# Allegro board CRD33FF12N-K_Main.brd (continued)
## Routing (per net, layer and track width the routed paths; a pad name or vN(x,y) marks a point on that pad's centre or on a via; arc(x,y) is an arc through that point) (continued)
DC_L_+: length 139.9
  TOP w0.254: v1(149.78,3.36) 149.78,2.94 150.96,1.76 262.25,1.76 263.01,2.52 J6.3
  BOTTOM w0.254: v1(149.78,3.36) 149.15,3.99 147.34,3.99 136.79,14.53 136.79,19.68 R161.2
DC_L_-: length 142.4
  TOP w0.254: J6.5 265.21,3.99 262.47,1.25 150.75,1.25 148.75,3.25 v1(148.62,3.25)
  BOTTOM w0.254: v1(148.62,3.25) 147.36,3.25 136.28,14.32 136.28,19.79 R117.2
DC_N: length 99
  ART04 w0.508: 407.04,36.45 407.04,34.42 402.47,29.84 402.47,18.03 397.19,12.75 378.65,12.75 v1(378.59,12.7)
  BOTTOM w0.254: 156.74,178.45 157.23,177.96 v1(157.78,177.96)
  BOTTOM w0.508: R130.2 218.79,193.37 C45.2 ; R99.1 v1(240.93,25.03) ; C50.1 207.21,43.78 206.35,42.93 R131.1 ; R87.1 171.44,40.55 174.26,43.37 174.26,43.49 174.66,43.9 174.78,43.9 C49.1 ; C46.2 178.61,198.9 178.61,209.97 R100.1 ; v1(378.59,12.7) 377.18,11.29 R139.1
  vias: v1(144.9,84.97) v1(144.9,83.27) v1(145.72,85.88) v1(147.42,85.88) v1(147.84,65.86) v1(147.9,64.64) v1(148.79,63.88) v1(149.05,67.06) v1(149.13,166.12) v1(149.19,164.9) v1(150.08,164.13) v1(150.19,63.75) v1(150.34,167.31) v1(150.57,66.8) v1(150.75,145.76) v1(151.08,64.39) v1(151.21,65.79) v1(151.48,164.01) v1(151.86,167.06) v1(152.12,145.76) v1(152.37,164.64) v1(152.5,166.04) v1(155.08,53.28) v1(155.08,43.08) v1(155.21,52.26) v1(155.21,42.06) v1(155.66,189.11) v1(155.66,178.91) v1(155.74,188.02) v1(155.74,177.82) v1(156.1,53.91) v1(156.1,51.75) v1(156.1,43.71) v1(156.1,41.55) v1(156.39,189.75) v1(156.39,179.55) v1(156.73,187.47) v1(156.73,177.27) v1(157.11,53.41) v1(157.11,52.26) v1(157.11,43.21) v1(157.11,42.06) v1(157.44,189.51) v1(157.44,179.31) v1(157.78,188.16) v1(166.22,84.97) v1(166.22,83.27) v1(167.04,85.88) v1(168.74,85.88) v1(171.96,145.76) v1(173.33,145.76) v1(174.05,43.97) v1(174.09,45.44) v1(174.94,43.21) v1(175.2,46.38) v1(176.34,43.08) v1(176.72,46.13) v1(177.23,43.72) v1(177.36,45.11) v1(183.9,192.69) v1(183.86,191.22) v1(184.75,190.46) v1(185.01,193.63) v1(186.15,190.33) v1(186.53,193.38) v1(187.04,190.96) v1(187.17,192.36) v1(187.54,84.97) v1(187.54,83.27) v1(188.36,85.88) v1(190.06,85.88) v1(193.17,145.76) v1(194.54,145.76) v1(205.63,45.44) v1(205.59,43.97) v1(206.48,43.21) v1(206.74,46.38) v1(207.88,43.08) v1(208.26,46.13) v1(208.77,43.72) v1(208.89,45.11) v1(215.84,191.22) v1(215.88,192.69) v1(216.73,190.46) v1(216.98,193.63) v1(218.13,190.33) v1(218.51,193.38) v1(219.02,190.96) v1(219.14,192.36) v1(243.05,198.23) v1(243.05,188.33) v1(243.09,199.7) v1(243.09,189.8) v1(243.94,197.47) v1(243.94,187.57) v1(244.19,200.64) v1(244.19,190.74) v1(245.33,197.34) v1(245.33,187.44) v1(245.71,200.39) v1(245.71,190.49) v1(246.22,197.97) v1(246.22,188.07) v1(246.35,199.37) v1(246.35,189.47) v1(248.05,198.23) v1(248.05,188.33) v1(248.09,199.7) v1(248.09,189.8) v1(248.94,197.47) v1(248.94,187.57) v1(249.19,200.64) v1(249.19,190.74) v1(250.33,197.34) v1(250.33,187.44) v1(250.55,21.53) v1(250.55,16.53) v1(250.59,23) v1(250.59,18) v1(250.71,200.39) v1(250.71,190.49) v1(251.22,197.97) v1(251.22,188.07) v1(251.35,199.37) v1(251.35,189.47) v1(251.44,20.77) v1(251.44,15.77) v1(251.69,23.94) v1(251.69,18.94) v1(252.83,20.64) v1(252.83,15.64) v1(253.22,23.69) v1(253.22,18.69) v1(253.72,21.28) v1(253.72,16.28) v1(253.85,22.67) v1(253.85,17.67) v1(260.45,21.53) v1(260.45,16.53) v1(260.49,23) v1(260.49,18) v1(261.34,20.77) v1(261.34,15.77) v1(261.59,23.94) v1(261.59,18.94) v1(262.73,20.64) v1(262.73,15.64) v1(263.12,23.69) v1(263.12,18.69) v1(263.62,21.28) v1(263.62,16.28) v1(263.75,22.67) v1(263.75,17.67) v1(412.42,188.26) v1(412.42,183.26) v1(412.67,189.78) v1(412.67,184.78) v1(413.36,187.16) v1(413.36,182.16) v1(413.69,190.42) v1(413.69,185.42) v1(414.83,187.12) v1(414.83,182.12) v1(415.08,190.29) v1(415.08,185.29) v1(415.59,188.01) v1(415.59,183.01) v1(415.72,189.4) v1(415.72,184.4) v1(418.98,164.59) v1(418.98,133.48) v1(418.98,101.73) v1(418.98,69.98) v1(418.98,38.86) v1(419.11,163.58) v1(419.11,132.46) v1(419.11,100.71) v1(419.11,68.96) v1(419.11,37.85) v1(420,165.23) v1(420,163.07) v1(420,134.11) v1(420,131.95) v1(420,102.36) v1(420,100.2) v1(420,70.61) v1(420,68.45) v1(420,39.5) v1(420,37.34) v1(421.01,164.72) v1(421.01,163.58) v1(421.01,133.6) v1(421.01,132.46) v1(421.01,101.85) v1(421.01,100.71) v1(421.01,70.1) v1(421.01,68.96) v1(421.01,38.99) v1(421.01,37.85) v1(422.32,188.26) v1(422.32,183.26) v1(422.57,189.78) v1(422.57,184.78) v1(423.26,187.16) v1(423.26,182.16) v1(423.59,190.42) v1(423.59,185.42) v1(424.73,187.12) v1(424.73,182.12) v1(424.98,190.29) v1(424.98,185.29) v1(425.49,188.01) v1(425.49,183.01) v1(425.62,189.4) v1(425.62,184.4) v1(427.91,188.39) v1(427.91,183.39) v1(428.16,189.91) v1(428.16,184.91) v1(428.85,187.28) v1(428.85,182.28) v1(429.18,190.55) v1(429.18,185.55) v1(430.32,187.24) v1(430.32,182.24) v1(430.58,190.42) v1(430.58,185.42) v1(431.09,188.13) v1(431.09,183.13) v1(431.21,189.53) v1(431.21,184.53) v1(437.81,188.39) v1(437.81,183.39) v1(438.06,189.91) v1(438.06,184.91) v1(438.75,187.28) v1(438.75,182.28) v1(439.08,190.55) v1(439.08,185.55) v1(440.22,187.24) v1(440.22,182.24) v1(440.48,190.42) v1(440.48,185.42) v1(440.99,188.13) v1(440.99,183.13) v1(441.11,189.53) v1(441.11,184.53) v1(443.28,188.26) v1(443.28,183.26) v1(443.53,189.78) v1(443.53,184.78) v1(444.22,187.16) v1(444.22,182.16) v1(444.55,190.42) v1(444.55,185.42) v1(445.69,187.12) v1(445.69,182.12) v1(445.94,190.29) v1(445.94,185.29) v1(446.45,188.01) v1(446.45,183.01) v1(446.58,189.4) v1(446.58,184.4) v1(453.18,188.26) v1(453.18,183.26) v1(453.43,189.78) v1(453.43,184.78) v1(454.12,187.16) v1(454.12,182.16) v1(454.45,190.42) v1(454.45,185.42) v1(455.59,187.12) v1(455.59,182.12) v1(455.84,190.29) v1(455.84,185.29) v1(456.35,188.01) v1(456.35,183.01) v1(456.48,189.4) v1(456.48,184.4)
DRV_COM1: length 13.9
  ART04 w0.508: v1(82.99,160.32) 76.11,160.32 74.03,162.4 v1(74.03,162.41)
  BOTTOM w0.381: R12.2 v1(81.89,156.44)
  BOTTOM w0.508: R14.2 101.89,155.83 v1(101.89,156.62) ; R24.2 v1(122.45,156.46)
  vias: v1(82.13,159.31) v1(83.57,159.31)
DRV_COM2: length 16.3
  BOTTOM w0.508: v1(147.89,156.16) 148.77,155.28 R42.2 ; R44.2 191.45,155.97 v1(191.45,156.08) ; 168.46,160.27 168.74,160.27 169.23,159.78 174.33,159.78 174.62,159.5 177.52,159.5 178.71,160.69 C108.1 ; R43.2 170.94,155.1 169.65,156.39 v1(169.27,156.39)
  vias: v1(167.32,159.33) v1(168.03,159.33)
DRV_COM3: length 22.4
  BOTTOM w0.508: C120.1 190.71,66.53 187.23,70 183.42,70 182.79,70.63 182.79,72.36 182.26,72.89 180.62,72.89 180.29,72.56 ; R73.2 v1(194.79,75.8) ; R69.2 153.2,78.21 v1(152,78.21) ; v1(174.53,77.62) 175.31,77.62 R71.2
  vias: v1(178.42,73.13) v1(179.05,73.13)
DRV_COM4: length 37.8
  BOTTOM w0.508: R124.2 125.57,76.71 v1(119.51,76.71) ; v1(107.17,75.9) 105.94,77.12 R123.2 ; v1(108.31,73.25) 108.36,73.25 ; 108.36,73.25 v1(108.95,73.25) 108.9,73.2 108.9,73.07 108.67,72.85 ; 108.36,73.25 108.67,72.95 108.67,72.85 ; 108.67,72.85 C40.2 106.97,72.58 C30.1 106.94,72.6 106.94,72.9 106.07,73.77 101.78,73.77 99.69,71.68 99.69,68.84 99.16,68.31 88.37,68.31 C128.1 ; v1(85.2,78.38) 84.25,77.44 R122.2
DRV_COM5: length 41.9
  BOTTOM w0.254: 251.85,158.88 251.85,158.89 ; 236.1,159 236.23,159.13
  BOTTOM w0.508: C18.1 C12.2 ; R34.2 244.5,157.79 243.92,158.37 236.74,158.37 236.56,158.54 ; R32.2 224.86,157.54 226.07,158.75 234.7,158.75 ; 236.23,159.13 236.25,159.13 236.28,159.16 236.84,159.16 236.87,159.13 236.97,159.03 247.38,159.03 248.55,157.86 250.83,157.86 251.85,158.88
DRV_COM6: length 49.3
  BOTTOM w0.508: C135.1 247.22,68.24 245.36,70.09 240.78,70.09 239.1,71.77 239.09,71.77 237.59,73.26 235.89,73.26 235.26,72.63 235.26,72.39 ; 234.13,72.51 234.13,73.04 235.68,74.59 246.47,74.59 R63.2 ; R61.2 227.05,78.49 232.18,78.49 234.78,75.9 234.78,74.91 233.21,73.34 233.21,72.26
DRV_G11: length 16.4
  BOTTOM w0.508: R9.1 77.28,152.47 R11.2 ; R11.2 74.82,152.44 R17.1 ; R11.2 77.73,151.95 Q11.4 77.73,146.6 75.79,144.65 R91.2 75.79,143.62 76.63,142.77 R94.2
DRV_G12: length 15.7
  BOTTOM w0.508: R5.1 R1.1 R2.2 98.94,152.37 Q12.4 98.94,146.1 97.6,144.76 R93.2 97.6,143.64 98.52,142.72 R173.2
DRV_G13: length 15.9
  BOTTOM w0.508: R169.2 119.47,142.78 118.66,143.59 R92.2 118.66,144.68 120.15,146.18 Q13.4 120.15,152.24 R8.2 R6.1 R4.1
DRV_G21: length 15.7
  BOTTOM w0.508: R37.1 R28.2 R27.1 146.48,148.21 Q21.4 146.28,145.81 145.41,144.93 R174.2 145.41,143.39 145.97,142.82 R177.2
DRV_G22: length 15.7
  BOTTOM w0.508: R31.2 168,152.14 ; 168,152.14 168,151.59 167.49,151.08 Q22.4 167.49,145.7 166.59,144.79 R176.2 166.59,143.33 167.07,142.85 R178.2 ; 168,152.14 R29.1 R36.1
DRV_G23: length 15.3
  BOTTOM w0.508: 189.21,152.26 R35.1 R40.2 ; 189.21,152.26 188.7,151.76 Q23.4 188.7,146.04 187.77,145.11 R175.2 187.77,143.87 188.7,142.95 R170.2 ; 189.21,152.26 R38.1
DRV_G31: length 16.4
  BOTTOM w0.508: R182.2 157.9,89.38 159.12,88.17 R179.2 159.12,87.5 158.26,86.64 157.32,86.64 156.78,86.1 Q31.4 156.42,83.8 156.42,80.19 R45.1 158.65,80.14 158.71,80.19 R48.2 R64.1
DRV_G32: length 15.5
  BOTTOM w0.508: Q32.4 178.09,85.83 179.68,87.42 R118.2 179.68,88.34 178.73,89.29 R183.2 ; Q32.4 178.09,80.15 R51.1 R55.2 R62.1 ; Q32.4 178.03,84.1
DRV_G33: length 15.3
  BOTTOM w0.508: R66.1 199.41,80.09 Q33.4 199.41,85.99 200.95,87.53 R180.2 200.95,88.24 199.88,89.31 R171.2 ; R66.1 R68.2 ; R66.1 R58.1
DRV_G41: length 15.9
  BOTTOM w0.508: R187.2 88.1,89.4 88.86,88.64 R184.2 88.86,87.51 87.89,86.55 Q41.4 87.89,81.72 86.54,80.36 R77.2 R74.1 R90.1
DRV_G42: length 16.6
  BOTTOM w0.508: R78.1 109.21,81.13 Q42.4 109.21,85.43 110.17,86.39 110.17,87.76 R186.2 110.15,88.64 109.58,89.2 R188.2 ; R78.1 R79.2 112.78,80.14 R84.1 ; R78.1 108.26,80.11 109.28,80.11
DRV_G43: length 15.1
  BOTTOM w0.508: R95.1 130.53,80.25 Q43.4 130.53,86.12 131.51,87.09 R185.2 131.51,88.58 130.78,89.31 R172.2 ; R95.1 130.35,80.1 R121.2 ; R95.1 132.63,80.09 R80.1
DRV_G51: length 11
  BOTTOM w0.508: 220.16,152.49 R16.1 ; 220.16,152.49 220.04,152.49 219.83,152.29 Q51.4 219.83,145.53 220.38,144.99 R83.2 ; 220.16,152.49 R18.2
DRV_G52: length 10.8
  BOTTOM w0.508: 241.55,152.24 241.09,152.24 241.09,152.24 R15.1 ; 241.55,152.24 241.55,151.27 241.04,150.77 Q52.4 241.6,147.45 R85.2 ; 241.55,152.24 R23.2
DRV_G61: length 10.5
  BOTTOM w0.508: R53.2 230.4,79.96 R50.1 230.39,80.87 229.89,81.37 Q61.4 229.89,87.65 R88.2
DRV_G62: length 10.4
  BOTTOM w0.508: R49.1 R59.2 251.2,80.28 Q62.4 251.2,87.5 R89.2
DRV_GATE1: length 7.1
  ART04 w0.508: v1(85.6,163.75) v1(83.52,163.75)
  BOTTOM w0.508: R22.1 85.98,162.63 85.98,163.38 v1(85.6,163.75) ; U1.6 v1(83.52,163.75)
DRV_GATE2: length 10.3
  BOTTOM w0.508: U3.6 168.38,163.9 167.56,164.72 164.93,164.72 162.71,162.5 R39.1
DRV_GATE3: length 20.1
  ART05 w0.508: v1(188.86,69.65) 185.34,66.13 v1(182.12,66.13)
  BOTTOM w0.508: R67.1 186.91,71.59 v1(188.86,69.65) ; v1(182.12,66.13) 179.8,66.13 178.04,67.9 U4.6
DRV_GATE4: length 11.2
  ART05 w0.508: v1(107.34,69.24) 107.34,68.99 107.84,68.48 109.02,68.48 109.53,68.99 109.53,71.14 v1(112.03,73.63)
  BOTTOM w0.508: U6.6 v1(107.34,69.24) ; v1(112.03,73.63) R96.1
DRV_Q1_-3V: length 26
  BOTTOM w0.508: C7.1 80.54,160.84 80.98,161.29 U1.8 80.98,163.07 80.43,163.62 C5.1 75.88,161.38 68.01,161.38 66.2,163.18 C91.2
DRV_Q2_+15V: length 4
  BOTTOM w0.254: 178.85,166.09 C101.2
  BOTTOM w0.508: 178.85,166.09 178.34,165.58 R191.1
DRV_Q2_-3V: length 28.4
  ART05 w0.508: v1(177.16,158.69) 176.89,158.97 v1(176.89,160.32) 175.37,161.83 167.87,161.83 v1(165.56,159.53)
  BOTTOM w0.508: v1(177.16,158.69) 180,158.69 181.51,160.21 C108.2 ; v1(165.56,159.53) C20.1 165.56,160.91 165.84,161.18 U3.8 ; C17.1 175.37,161.83 v1(176.89,160.32)
DRV_Q3_+15V: length 9.3
  BOTTOM w0.508: C110.2 188.85,58.25 188.34,58.76 188.34,61.43 R193.1
DRV_Q3_-3V: length 17
  ART05 w0.508: v1(193.13,66.84) 189.18,66.84 v1(188.95,67.07)
  BOTTOM w0.508: C29.1 181.6,71.38 180.58,70.35 U4.8 180.58,69.09 180.83,68.83 C25.1 183.73,69.07 186.95,69.07 v1(188.95,67.07)
DRV_Q4_+15V: length 11.1
  BOTTOM w0.508: C128.2 88.77,70.71 89.29,70.71 90.38,69.62 R194.1
DRV_Q4_-3V: length 30.8
  BOTTOM w0.254: C40.1 110.19,72.57 110.23,72.53
  BOTTOM w0.508: C138.2 86.8,64.98 89.87,64.98 91.71,66.82 99.88,66.82 100.94,67.87 C34.1 109.14,67.87 109.88,68.61 U6.8 109.88,72.05 110.23,72.41 110.23,72.59
DRV_Q5_+15V: length 2.9
  BOTTOM w0.508: R190.1 248.34,159.95 C118.1
DRV_Q5_-3V: length 39.8
  BOTTOM w0.508: C18.2 233.37,160.83 233.62,161.09 U2.8 233.62,163.65 234.66,164.69 239.02,164.69 C16.2 241.24,163.53 247.76,170.05 256.24,170.05 257.02,169.28 257.02,163.1 256.54,162.62 C126.2
DRV_Q6_-3V: length 28.2
  ART05 w0.508: v1(240.67,71.36) 239.16,71.36 v1(238.76,70.95)
  BOTTOM w0.508: U5.8 235.7,70.52 236.47,71.29 236.47,72.11 236.47,72.12 C35.2 237.3,72.16 237.34,72.12 237.6,72.12 v1(238.76,70.95) 239.34,70.38 C33.2 ; C144.2 251.14,62.96 251.9,63.72 251.9,67.22 247.77,71.36 v1(240.67,71.36)
DRV_S11: length 11.2
  BOTTOM w0.508: R94.1 78.98,142.77 80.15,143.94 C19.1 80.15,147.89 Q11.3 80.27,150.65 81.89,152.27 R12.1
DRV_S12: length 10.8
  BOTTOM w0.508: R173.1 100.79,142.72 101.99,143.92 C54.1 101.99,144.91 101.48,145.42 Q12.3 101.48,152.26 R14.1
DRV_S13: length 10.9
  BOTTOM w0.508: R169.1 122.31,142.78 123.03,143.49 C39.1 123.03,145.03 122.69,145.36 Q13.3 122.69,152.12 R24.1
DRV_S21: length 11
  BOTTOM w0.508: R42.1 148.82,152.31 Q21.3 148.82,145.56 149.8,144.59 C64.1 149.8,143.53 149.09,142.82 R177.1
DRV_S22: length 11.3
  BOTTOM w0.508: R43.1 170.03,151.23 Q22.3 170.03,145.66 170.98,144.71 C66.1 170.98,143.18 170.65,142.85 R178.1
DRV_S23: length 11.1
  BOTTOM w0.508: R170.1 191.27,142.95 192.14,143.82 C65.1 192.14,144.9 191.24,145.79 Q23.3 191.24,150.93 192.35,152.03 R44.1
DRV_S31: length 10.2
  BOTTOM w0.508: R69.1 154.24,80.31 Q31.3 154.24,87.34 C70.1 154.75,88.1 156.04,89.38 R182.1
DRV_S32: length 10
  BOTTOM w0.508: R71.1 175.64,84.07 Q32.3 175.55,87.66 C146.1 175.37,88.08 176.58,89.29 R183.1
DRV_S33: length 11.3
  BOTTOM w0.508: R73.1 196.87,82.13 Q33.3 196.87,87.57 C145.1 196.59,88.55 197.34,89.31 198.03,89.31
DRV_S41: length 11.2
  BOTTOM w0.508: R187.1 85.11,89.4 84.32,88.61 C162.1 84.32,87.16 85.35,86.13 Q41.3 85.35,81.25 R122.1
DRV_S42: length 10.9
  BOTTOM w0.508: 105.71,87.78 105.71,87.13 106.67,86.17 Q42.3 107.03,83.8 107.03,81.23 R123.1 ; 105.71,87.78 C164.1 105.71,87.78 ; 105.71,87.78 105.71,88.05 106.86,89.2 R188.1
DRV_S43: length 11.3
  BOTTOM w0.508: R172.1 127.89,89.31 127.11,88.52 C163.2 127.11,86.98 127.99,86.09 127.99,82.13 126.16,80.3 R124.1
DRV_S51: length 9.5
  BOTTOM w0.508: R83.1 221.89,144.9 222.37,145.38 Q51.3 222.37,150.1 224.76,152.49 R32.1
DRV_S52: length 8.7
  BOTTOM w0.508: R34.1 244.5,152.14 243.48,151.12 243.48,148.11 Q52.3 243.12,147.55 R85.1
DRV_S61: length 8.9
  BOTTOM w0.508: R88.1 227.35,87.1 Q61.3 227.29,84.11 227.29,81.54 R61.1
DRV_S62: length 8.3
  BOTTOM w0.508: R89.1 248.66,87.27 Q62.3 248.66,80.54 R63.1
FAN_GND: length 0
  vias: v1(4.78,175.69) v1(6.23,174.65) v1(7.81,173.56)
GATE5: length 31.2
  ART04 w0.508: v1(243.57,157.2) 240,157.2 v1(236.16,161.04) 235.27,161.93 233.56,161.93 v1(232.54,160.91)
  BOTTOM w0.508: R23.1 242.21,156.56 242.72,157.07 243.44,157.07 v1(243.57,157.2) ; R18.1 222.45,156.81 225.65,160.02 231.66,160.02 v1(232.54,160.91) ; U2.6 v1(236.16,161.04)
GATE6: length 32.4
  ART05 w0.508: v1(230.53,71.18) 230.54,71.17 v1(233.16,71.17) 233.22,71.17 234.09,70.3 236.52,70.3 238.54,72.32 v1(239.82,72.32)
  BOTTOM w0.508: v1(230.53,71.18) 230.53,73.72 228.13,76.12 R53.1 ; v1(239.82,72.32) 246.48,72.32 251.42,77.27 R59.1 ; U5.6 v1(233.16,71.17)
GGND: length 745.5
  TOP w0.762: v1(220.89,23.72) 219.39,23.72 218.2,22.53 v1(216.16,22.53) ; v1(197.3,179.86) 199.72,179.86 201.14,181.28 257.12,181.28 260.88,177.53 v1(260.88,176.46)
  GND02 w0.762: v1(197.3,179.86) 177.63,179.86 175.37,182.13 175.37,202.61 166.61,211.37 37.64,211.37 32.95,206.68 32.95,182.36 v1(36,179.31)
  ART03 w0.508: J5.6 162.36,7.46 162.36,10.03
  ART03 w0.762: v1(216.16,22.53) 200.05,22.53 191.57,14.05 166.38,14.05 162.36,10.03 ; J5.6 161.08,6 159.51,4.44 153.15,4.44 145.5,12.09 113.74,12.09 112.24,10.59 107.56,10.59 106.97,11.19 106.97,11.2 106.71,11.46 v1(106.71,12.78) ; v1(57.63,59.52) 57.63,59.55 56.53,60.65 56.53,96.8 69.26,109.53 69.26,123.02 54.21,138.07 54.21,158.75 59.52,164.05 v1(59.77,164.05)
  BOTTOM w0.762: v1(106.71,12.78) 106.71,17.42 103.16,20.97 69.54,20.97 55.54,34.97 55.54,57.43 v1(57.63,59.52) ; C139.2 239.53,31.41 237.49,31.41 229.79,23.72 v1(220.89,23.72) ; v1(197.3,179.86) 197.34,179.83 197.34,177.56 198.39,176.51 C103.2 ; v1(36,179.31) 36.12,179.2 36.12,176.61 36.92,175.81 58.84,175.81 60.45,174.2 60.45,164.73 v1(59.77,164.05) 59.36,164.05 58.58,164.83 57.75,164.83 ; v1(260.88,176.46) C121.2
  BOTTOM w0.78: C112.2 217.22,48.45 217.22,25.81 216.16,24.75 v1(216.16,22.53)
IGND: length 99
  TOP w0.762: J2.1 81.31,6.99 86.15,6.99 86.69,6.45 96.32,6.45 98.04,4.74 C157.2 117.53,4.74 123.28,10.49 149.93,10.49 152.04,12.6 164.9,12.6 167.87,9.63 167.87,7.89 J5.2
IL+: length 132.9
  TOP w0.254: R75.1 380.14,6.59 379.83,6.59 379.82,6.59 376.02,6.59 369.25,13.35 362.22,13.35 359.36,16.21 272.29,16.21 265.82,9.74 262.94,9.74 260.98,7.78 260.1,7.78 259.23,6.9 259.23,5.23 J6.1
IL-: length 128.2
  TOP w0.254: J6.2 263.04,9.09 266.04,9.09 272.64,15.7 359.15,15.7 362.01,12.84 369.04,12.84 375.81,6.08 380.14,6.08 R76.1
MID_N:
  vias: v1(76.02,84.97) v1(76.02,83.27) v1(76.93,82.45) v1(78.63,82.45) v1(97.34,84.97) v1(97.34,83.27) v1(98.25,82.45) v1(99.95,82.45) v1(118.65,84.97) v1(118.65,83.27) v1(119.56,82.45) v1(121.27,82.45) v1(151.08,81.91) v1(152.45,81.91) v1(172.4,81.91) v1(173.77,81.91) v1(193.71,81.91) v1(195.08,81.91) v1(224.19,81.91) v1(225.56,81.91) v1(245.51,81.91) v1(246.88,81.91)
MID_P:
  vias: v1(82.06,150.27) v1(83.43,150.27) v1(103.27,150.27) v1(104.64,150.27) v1(124.48,150.27) v1(125.85,150.27) v1(155.55,149.73) v1(157.25,149.73) v1(158.16,148.91) v1(158.16,147.2) v1(176.76,149.73) v1(178.46,149.73) v1(179.37,148.91) v1(179.37,147.2) v1(197.97,149.73) v1(199.67,149.73) v1(200.58,148.91) v1(200.58,147.2) v1(229.1,149.73) v1(230.8,149.73) v1(231.71,148.91) v1(231.71,147.2) v1(250.31,149.73) v1(252.01,149.73) v1(252.92,148.91) v1(252.92,147.2)
NETC1_2: length 5.6
  BOTTOM w0.508: R3.2 77.6,173.66 C2.1 C1.2 80.68,173.58 80.98,173.28 U1.1
NETC3_2: length 8.8
  BOTTOM w0.254: R10.2 86.14,173.96 R7.2 86.14,175.55 85.28,176.4 83.55,176.4 83.15,176.01 C3.2 83.1,175.31 82.25,174.46 U1.2
NETC4_2: length 14.5
  BOTTOM w0.508: R189.2 76.2,163.79 77.82,165.4 C5.2 83.84,165.4 84.79,164.44 U1.5 84.79,161.28 85.1,160.97 85.38,160.69 C4.2
NETC8_2: length 5.5
  BOTTOM w0.508: U2.1 233.62,173.19 233.37,173.44 C8.2 C9.1 229.94,174.84 R19.2
NETC10_2: length 8.2
  BOTTOM w0.254: U2.2 234.89,174.12 C10.2 236.04,175.31 236.84,176.11 238.79,176.11 239.04,175.86 R21.2 239.05,175.28 R25.2
NETC11_2: length 5.4
  BOTTOM w0.508: R26.2 162.35,175.3 C13.1 C11.2 165.33,173.78 165.84,173.28 U3.1
NETC12_1: length 10.9
  BOTTOM w0.508: R190.2 243.27,161.14 242.66,161.75 C16.1 239.76,161.75 238.37,163.14 237.86,163.14 237.43,162.72 U2.5 237.43,160.85 237.94,160.34 C12.1
NETC14_2: length 8.8
  BOTTOM w0.254: U3.2 167.11,174.19 168.31,175.4 C14.2 168.31,175.96 168.82,176.46 170.92,176.46 171.36,176.03 R30.2 171.36,174.05 R33.2
NETC15_2: length 9.1
  BOTTOM w0.508: C15.2 169.95,160.82 169.95,161.36 169.65,161.67 U3.5 169.65,164.54 170.69,165.58 R191.2 172.46,165.57 C17.2
NETC19_2: length 1.3
  BOTTOM w0.508: R91.1 C19.2
NETC21_2: length 15.8
  BOTTOM w0.508: R193.2 183.61,66.94 C25.2 183.12,66.68 183.12,65.75 182.61,65.25 178.94,65.25 176.77,67.42 U4.5 176.77,71.72 C21.2
NETC22_2: length 5.3
  BOTTOM w0.508: U4.1 181.07,58.7 C22.2 C23.1 184.09,58.66 R41.2
NETC24_2: length 8.6
  BOTTOM w0.254: U4.2 179.31,58.09 C24.2 178.13,56.31 177.87,56.05 175.36,56.05 175.1,56.31 R46.2 175.1,58.32 R52.2
NETC26_2: length 5.5
  BOTTOM w0.508: R54.2 238.72,58.03 C27.1 C26.2 236.2,58.08 235.7,58.58 U5.1
NETC30_2: length 7.6
  BOTTOM w0.508: R194.2 102.13,69.62 102.16,69.65 C34.2 103.5,69.65 104.48,70.63 U6.5 106.07,71.81 105.67,72.2 105.67,72.36 C30.2
NETC31_2: length 8.7
  BOTTOM w0.254: R60.2 230.29,57.71 230.28,57.7 230.28,57.54 230.26,57.53 R57.2 230.26,56.55 230.87,55.94 232.36,55.94 233.24,56.82 C31.2 233.94,56.92 234.43,57.41 U5.2
NETC32_1: length 14
  BOTTOM w0.508: C32.1 231.91,71.34 231.9,71.34 231.9,71.13 231.89,71.12 U5.5 231.89,68.48 232.98,67.38 C33.1 240.67,67.38 R192.2
NETC36_2: length 5.4
  BOTTOM w0.508: R65.2 113.47,58.15 113.47,59.33 C37.1 112.64,59.38 112.63,59.39 C36.2 111.31,59.39 110.67,60.03 U6.1
NETC38_2: length 8.6
  BOTTOM w0.254: U6.2 108.61,58.63 107.67,57.7 C38.2 107.07,57.67 106.14,56.74 104.97,56.74 R70.2 104.02,59.11 R72.2
NETC39_2: length 1.3
  BOTTOM w0.508: C39.2 R92.1
NETC43_2: length 9.8
  BOTTOM w0.508: R128.1 218.88,200.6 C45.1 ; 74.61,203.83 72.35,203.83 C43.2
  vias: v1(68.86,202.58) v1(68.82,201.11) v1(69.71,200.35) v1(69.97,203.52) v1(71.11,200.22) v1(71.49,203.27) v1(72,200.86) v1(72.13,202.25) v1(100.02,202.67) v1(99.99,201.2) v1(100.88,200.43) v1(101.13,203.61) v1(102.27,200.31) v1(102.65,203.36) v1(103.16,200.94) v1(103.29,202.34) v1(183.9,202.69) v1(183.86,201.22) v1(184.75,200.46) v1(185.01,203.63) v1(186.15,200.33) v1(186.53,203.38) v1(187.04,200.96) v1(187.17,202.36) v1(215.84,201.22) v1(215.88,202.69) v1(216.73,200.46) v1(216.98,203.63) v1(218.13,200.33) v1(218.51,203.38) v1(219.02,200.96) v1(219.14,202.36)
NETC49_2: length 11.3
  BOTTOM w0.508: C50.2 203.15,34.78 R165.2 ; R167.2 69.71,36.07 C52.1
  vias: v1(66.56,35.16) v1(66.52,33.69) v1(67.41,32.93) v1(67.67,36.1) v1(68.81,32.8) v1(69.19,35.85) v1(69.7,33.44) v1(69.83,34.83) v1(98.42,35.34) v1(98.38,33.87) v1(99.27,33.11) v1(99.52,36.28) v1(100.67,32.98) v1(101.05,36.03) v1(101.55,33.62) v1(101.68,35.01) v1(174.05,33.97) v1(174.09,35.44) v1(174.94,33.21) v1(175.2,36.38) v1(176.34,33.08) v1(176.72,36.13) v1(177.23,33.72) v1(177.36,35.11) v1(205.63,35.44) v1(205.59,33.97) v1(206.48,33.21) v1(206.74,36.38) v1(207.88,33.08) v1(208.26,36.13) v1(208.77,33.72) v1(208.89,35.11)
NETC54_2: length 1.4
  BOTTOM w0.508: C54.2 R93.1
NETC64_2: length 1.4
  BOTTOM w0.508: C64.2 R174.1
NETC65_2: length 1.3
  BOTTOM w0.508: R175.1 C65.2
NETC66_2: length 1.4
  BOTTOM w0.508: C66.2 R176.1
NETC70_2: length 1.3
  BOTTOM w0.508: R179.1 C70.2
NETC92_1: length 7.4
  TOP w0.508: Q15.3 286.86,5.82 287.37,6.33 R145.1 288.7,6.33 C92.1 289.66,7.29 v1(290.08,7.29)
  BOTTOM w0.381: v1(290.08,7.29) 289.95,7.41 U9.7
NETC145_2: length 1.3
  BOTTOM w0.508: C145.2 R180.1
NETC146_2: length 1.3
  BOTTOM w0.508: R118.1 176.89,87.85 C146.2
NETC152_1: length 23
  TOP w0.381: U16.1 406.08,4.1 404.16,2.19 394.57,2.19 393.58,3.17 C152.1 387.93,3.17 387.91,3.16 C153.1 R97.1
NETC154_1: length 13.5
  TOP w0.381: C154.1 391.78,6.58 392.45,7.25 399.82,7.25 400.08,6.99 U16.4
NETC155_1: length 4.2
  TOP w0.381: R75.2 382.17,7.09 C155.1 384.46,7.09 R98.1
NETC162_2: length 1.5
  BOTTOM w0.508: R184.1 85.85,87.99 C162.2
NETC163_1: length 1.4
  BOTTOM w0.508: R185.1 C163.1
NETC164_2: length 1.4
  BOTTOM w0.508: R186.1 C164.2
NETD1_1: length 2.4
  BOTTOM w0.508: R1.2 96.73,157.05 D1.1
NETD1_2: length 70.3
  ART04 w0.508: v1(83.34,157.76) 81.14,157.76 79.93,158.97 v1(76.74,158.97)
  BOTTOM w0.508: v1(76.74,158.97) D3.2 77.25,156.94 R11.1 ; R22.2 87.17,158.01 83.6,158.01 v1(83.34,157.76) ; R22.2 88.09,158.94 90.67,158.94 91.68,159.94 107.73,159.94 109.1,158.57 119.6,158.57 120.4,157.77 D2.2 120.03,156.98 R8.1 ; R22.2 88.2,157.61 92.23,157.61 93.45,158.83 99.96,158.83 100.47,158.32 D1.2 99.01,156.03 R2.1
NETD2_1: length 2.5
  BOTTOM w0.508: R6.2 117.76,156.69 D2.1
NETD3_1: length 2.4
  BOTTOM w0.508: R9.2 79.61,157.01 D3.1
NETD6_1: length 2.3
  BOTTOM w0.508: R27.2 146.48,156.84 D6.1
NETD6_2: length 60.8
  BOTTOM w0.508: R28.1 144.19,156.68 D6.2 143.61,157.62 144.52,158.53 158.94,158.53 160.33,157.14 160.33,155.51 162.28,153.56 167.07,153.56 167.54,154.03 167.54,154.03 168.44,154.94 R31.1 ; R31.1 167.95,155.64 D7.2 167.71,157.18 166.19,157.18 165.32,158.05 163.05,158.05 R39.2 ; R31.1 170.03,153.56 171.95,153.56 173.46,155.06 R40.1 185.54,155.49 D8.2
NETD7_1: length 2.6
  BOTTOM w0.508: R29.2 165.67,155.5 165.67,155.83 164.65,156.84 D7.1
NETD8_1: length 2.4
  BOTTOM w0.508: D8.1 190.07,156.71 R38.2
NETD9_1: length 2.3
  BOTTOM w0.508: R45.2 155.9,76.77 D9.1
NETD9_2: length 49.1
  BOTTOM w0.508: R48.1 159.2,76.9 D9.2 159.76,74.73 174.73,74.73 175.47,73.99 184.1,73.99 R67.2 ; R67.2 183.59,75.31 D10.2 181.06,75.36 181.06,76.56 R55.1 ; R67.2 191.8,74.39 192.39,74.98 196.33,74.98 D13.2 196.57,76.73 R68.1
NETD10_1: length 2.1
  BOTTOM w0.508: D10.1 178.03,75.63 R51.2
NETD13_1: length 2.2
  BOTTOM w0.508: D13.1 199.87,76.73 R66.2
NETD14_1: length 2.4
  BOTTOM w0.508: R74.2 89.47,76.83 D14.1
NETD14_2: length 62.9
  BOTTOM w0.508: D16.2 128.26,75.88 R121.1 128.26,77.51 127.14,78.63 125.13,78.63 124.17,77.67 117.85,77.67 115.37,75.19 114.83,75.19 ; 114.83,75.19 114.81,75.16 111.72,75.16 D15.2 111.61,75.75 110.51,76.84 R79.1 ; 114.83,75.19 114.83,78.25 114.32,78.76 104.95,78.76 102.9,76.71 94.67,76.71 92.58,78.8 87.98,78.8 R77.1 86.54,75.5 D14.2 ; 114.83,75.19 R96.2
NETD15_1: length 2.1
  BOTTOM w0.508: D15.1 108.31,76.35 108.23,76.42 R78.2
NETD16_1: length 2.3
  BOTTOM w0.508: R95.2 130.37,75.61 D16.1
NETL1_1:
  vias: v1(327.72,160.45) v1(327.72,159.18) v1(328.1,161.72) v1(328.23,158.29) v1(328.99,162.48) v1(329.24,157.53) v1(330.39,162.99) v1(330.77,157.15) v1(331.78,162.99) v1(332.42,157.15) v1(333.18,162.99) v1(333.69,157.15) v1(334.7,162.99) v1(334.92,157.13) v1(336.1,162.99) v1(336.23,157.15) v1(337.5,162.99) v1(337.75,157.15) v1(339.02,162.86) v1(339.53,157.4) v1(340.42,162.1) v1(340.55,158.17) v1(341.05,160.96) v1(341.18,159.56) v1(384.74,160.45) v1(384.74,159.18) v1(385.12,161.72) v1(385.25,158.29) v1(386.01,162.48) v1(386.27,157.53) v1(387.41,162.99) v1(387.79,157.15) v1(388.81,162.99) v1(389.44,157.15) v1(390.2,162.99) v1(390.71,157.15) v1(391.73,162.99) v1(391.95,157.13) v1(393.12,162.99) v1(393.25,157.15) v1(394.52,162.99) v1(394.77,157.15) v1(396.04,162.86) v1(396.55,157.4) v1(397.44,162.1) v1(397.57,158.17) v1(398.08,160.96) v1(398.2,159.56)
NETL1_2:
  vias: v1(327.71,91.81) v1(327.83,90.41) v1(328.34,93.2) v1(328.47,89.27) v1(329.36,93.97) v1(329.87,88.51) v1(331.14,94.22) v1(331.39,88.38) v1(332.66,94.22) v1(332.79,88.38) v1(333.42,92.95) v1(333.96,94.24) v1(334.18,88.38) v1(335.2,94.22) v1(335.71,88.38) v1(336.47,94.22) v1(337.11,88.38) v1(338.12,94.22) v1(338.5,88.38) v1(339.65,93.84) v1(339.9,88.89) v1(340.66,93.08) v1(340.8,136.45) v1(340.8,135.18) v1(340.79,89.65) v1(341.18,137.72) v1(341.17,92.19) v1(341.17,90.92) v1(341.31,134.29) v1(342.07,138.48) v1(342.32,133.53) v1(343.47,138.99) v1(343.85,133.15) v1(344.86,138.99) v1(345.5,133.15) v1(346.26,138.99) v1(346.77,133.15) v1(347.78,138.99) v1(348,133.13) v1(349.18,138.99) v1(349.31,133.15) v1(350.58,138.99) v1(350.83,133.15) v1(352.1,138.86) v1(352.61,133.4) v1(353.5,138.1) v1(353.63,134.16) v1(354.13,136.96) v1(354.26,135.56)
NETL2_1:
  vias: v1(283.77,67.8) v1(283.89,66.41) v1(284.4,69.2) v1(284.53,65.26) v1(285.42,69.96) v1(285.92,64.5) v1(287.19,70.22) v1(287.45,64.38) v1(288.72,70.22) v1(288.85,64.38) v1(290.02,70.24) v1(290.24,64.38) v1(291.26,70.22) v1(291.77,64.38) v1(292.53,70.22) v1(293.16,64.38) v1(294.18,70.22) v1(294.56,64.38) v1(295.7,69.84) v1(295.96,64.88) v1(296.72,69.07) v1(296.85,65.65) v1(297.23,68.19) v1(297.23,66.92) v1(340.79,67.8) v1(340.92,66.41) v1(341.42,69.2) v1(341.55,65.26) v1(342.44,69.96) v1(342.95,64.5) v1(344.22,70.22) v1(344.47,64.38) v1(345.74,70.22) v1(345.87,64.38) v1(347.05,70.24) v1(347.27,64.38) v1(348.28,70.22) v1(348.79,64.38) v1(349.55,70.22) v1(350.19,64.38) v1(351.2,70.22) v1(351.58,64.38) v1(352.73,69.84) v1(352.98,64.88) v1(353.74,69.07) v1(353.87,65.65) v1(354.25,68.19) v1(354.25,66.92)
NETL2_3:
  vias: v1(384.73,91.81) v1(384.86,90.41) v1(385.37,93.2) v1(385.49,89.27) v1(386.38,93.97) v1(386.89,88.51) v1(388.16,94.22) v1(388.41,88.38) v1(389.68,94.22) v1(389.81,88.38) v1(390.99,94.24) v1(391.21,88.38) v1(392.22,94.22) v1(392.73,88.38) v1(393.49,94.22) v1(394.13,88.38) v1(395.14,94.22) v1(395.53,88.38) v1(396.67,93.84) v1(396.92,88.89) v1(397.68,93.08) v1(397.81,89.65) v1(398.19,92.19) v1(398.19,90.92)
NETQ15_1: length 9.3
  TOP w0.508: Q15.1 283,6.77 283.51,6.26 283.51,5.7 283.99,5.22 283.99,5.21 284,5.2 284,4.66 285.03,3.63 287.55,3.63 R151.2 287.8,3.63 R149.1
NETR81_1: length 2.3
  BOTTOM w0.508: R114.2 138.02,211.25 138.03,211.25 R81.1
NETR82_1: length 2.3
  BOTTOM w0.508: R82.1 147.94,211.26 R105.2
NETR86_2: length 6.5
  BOTTOM w0.5: R106.1 108.7,36.32 R86.2
NETR87_2: length 3
  BOTTOM w0.5: R87.2 R120.1
NETR98_2: length 16
  TOP w0.381: R98.2 388.97,8.4 389.01,8.36 400.94,8.36 402.08,7.23 U16.3
NETR100_2: length 2.3
  BOTTOM w0.508: R100.2 R101.1
NETR101_2: length 2.3
  BOTTOM w0.508: R101.2 R102.1
NETR102_2: length 2.3
  BOTTOM w0.508: R102.2 R103.1
NETR103_2: length 2.3
  BOTTOM w0.508: R103.2 R104.1
NETR104_2: length 2.3
  BOTTOM w0.508: R104.2 R105.1
NETR106_2: length 2.2
  BOTTOM w0.5: R106.2 115.68,34.27 R107.1
NETR107_2: length 2.6
  BOTTOM w0.5: R108.1 116.25,31.37 R107.2
NETR108_2: length 2.9
  BOTTOM w0.5: R115.1 R108.2
NETR109_2: length 2.3
  BOTTOM w0.508: R109.2 R110.1
NETR110_2: length 2.3
  BOTTOM w0.508: R110.2 R111.1
NETR111_2: length 2.3
  BOTTOM w0.508: R111.2 R112.1
NETR112_2: length 2.3
  BOTTOM w0.508: R112.2 R113.1
NETR113_2: length 2.3
  BOTTOM w0.508: R113.2 R114.1
NETR115_2: length 4.9
  BOTTOM w0.508: R116.1 127.03,20.58 124.37,23.25 R115.2
NETR116_2: length 2.9
  BOTTOM w0.508: R116.2 130.92,20.58 130.93,20.57 R117.1
NETR120_2: length 3
  BOTTOM w0.5: R120.2 R157.1
NETR125_2: length 2.9
  BOTTOM w0.508: R125.2 79.61,198.1 R126.1
NETR126_2: length 2.2
  BOTTOM w0.508: R127.1 77.42,203.83 R126.2
NETR128_2: length 2.3
  BOTTOM w0.508: R129.1 224.55,198.63 R128.2
NETR129_2: length 2.4
  BOTTOM w0.508: R130.1 224.42,195.2 R129.2
NETR131_2: length 2.2
  BOTTOM w0.508: R132.1 199.32,40.77 R131.2
NETR132_2: length 2.2
  BOTTOM w0.508: R132.2 199.32,35.82 R165.1
NETR133_2: length 2.3
  BOTTOM w0.508: R134.1 R133.2
NETR134_2: length 2.3
  BOTTOM w0.508: R135.1 R134.2
NETR135_2: length 2.3
  BOTTOM w0.508: R136.1 R135.2
NETR136_2: length 2.4
  BOTTOM w0.508: R137.1 R136.2
NETR137_2: length 2.4
  BOTTOM w0.508: R138.1 R137.2
NETR139_2: length 2.3
  BOTTOM w0.508: R139.2 R140.1
NETR140_2: length 2.3
  BOTTOM w0.508: R140.2 R141.1
NETR141_2: length 2.4
  BOTTOM w0.508: 355.04,11.29 R142.1 355.04,11.29 ; 355.04,11.29 R141.2
NETR142_2: length 2.3
  BOTTOM w0.508: 349.9,11.28 R142.2 ; 349.9,11.28 R143.1 349.9,11.28
NETR143_2: length 2.4
  BOTTOM w0.508: R143.2 R144.1
NETR146_2: length 4.6
  TOP w0.508: v1(293.01,6.58) 293.01,6.24 293.32,5.94 R146.2 R148.2
  BOTTOM w0.381: U9.19 293.2,6.76 v1(293.01,6.58)
NETR150_2: length 2.7
  TOP w0.508: v1(290.08,8.23) R150.2
  BOTTOM w0.381: U9.8 289.91,8.06 v1(290.08,8.23)
NETR157_2: length 3
  BOTTOM w0.5: R157.2 R158.1
NETR158_2: length 3
  BOTTOM w0.5: R158.2 R159.1
NETR159_2: length 4.9
  BOTTOM w0.5: R159.2 R160.1
NETR160_2: length 2.7
  BOTTOM w0.5: R161.1 R160.2
NETR166_1: length 2.3
  BOTTOM w0.508: R168.2 76.21,41.28 76.08,41.15
NETR166_2: length 2.3
  BOTTOM w0.508: R166.2 76.08,36.1 R167.1
PWM-1A: length 57.7
  TOP w0.254: v1(231.75,55.16) 234.27,55.16 234.52,54.9 234.52,12.28 J3.2
  BOTTOM w0.254: v1(231.75,55.16) 229.84,55.16 228.74,56.26 R57.1
PWM-1B: length 632.5
  TOP w0.254: v1(205.58,17.75) 185.8,17.75 183.25,15.2 113.66,15.2 111.53,17.34 66.81,17.34 51.03,33.12 51.03,34.8 51.03,97.04 65.01,111.02 65.01,118.97 50.05,133.94 50.05,174.28 46.62,177.71 45.1,177.71 35.31,187.5 35.31,203.73 40.02,208.43 165.72,208.43 172.02,202.13 172.02,178.9 172.97,177.94 192.83,177.94 194,176.77 203.77,176.77 205.2,178.2 232.01,178.2 233.82,176.39 v1(240.56,176.39)
  BOTTOM w0.254: v1(205.58,17.75) 206.25,17.08 206.25,14.32 208.36,12.21 231.03,12.21 235.37,7.87 241.48,7.87 J3.4 ; R21.1 v1(240.56,176.39)
PWM-2A: length 410.5
  TOP w0.254: J3.6 246.63,5.26 248.65,5.26 249.29,4.63 249.29,3.15 248.4,2.27 237.72,2.27 228.58,11.41 217.77,11.41 209.22,19.96 195.65,19.96 194.61,21 184.84,21 181.88,18.04 115.16,18.04 113.83,19.37 67.65,19.37 53.06,33.96 53.06,96.13 67.12,110.19 67.12,120.42 v1(63.23,124.31)
  ART03 w0.254: v1(87.66,176.56) 83.42,176.56 82.14,177.83 53.81,177.83 52.2,176.21 52.2,135.34 v1(63.23,124.31)
  BOTTOM w0.254: v1(87.66,176.56) R7.1
PWM-2B: length 569.1
  TOP w0.254: v1(207.61,18.04) 207.21,18.44 185.77,18.44 183.04,15.71 113.87,15.71 111.74,17.85 67.02,17.85 51.54,33.33 51.54,96.83 65.52,110.81 65.52,119.18 50.56,134.15 50.56,174.49 50.26,174.79 46.83,178.22 45.31,178.22 35.82,187.71 35.82,203.52 40.23,207.92 165.45,207.92 171.51,201.87 171.51,178.13 v1(172.88,176.76)
  BOTTOM w0.254: J3.8 246.05,8.38 235.58,8.38 231.17,12.78 208.53,12.78 206.76,14.55 206.76,17.19 v1(207.61,18.04) ; R30.1 v1(172.88,176.76)
PWM-3A: length 105.7
  TOP w0.254: v1(174.02,55.89) 174.91,55 179.5,55 187.96,46.54 187.96,26.65 192.6,22.02 195.64,22.02 196.61,21.05 209.57,21.05 218.19,12.43 229.39,12.43 236.61,5.21 244.14,5.21 J3.5
  BOTTOM w0.254: v1(174.02,55.89) 173.58,56.32 R46.1
PWM-3B: length 193.8
  TOP w0.254: J3.7 247.9,3.86 246.82,2.78 237.93,2.78 228.79,11.92 217.98,11.92 209.43,20.47 196.14,20.47 195.11,21.51 184.45,21.51 181.49,18.55 115.6,18.55 114.52,19.63 114.52,29.17 111.29,32.4 111.29,57.89 110.74,58.44 109.19,58.44 107.42,56.67 v1(102.5,56.67)
  BOTTOM w0.254: R70.1 v1(102.5,56.67)
VA+5V: length 821.9
  TOP w0.508: R145.2 286.66,7.85 v1(286.66,7.85)
  TOP w0.762: 51.29,179.18 51.43,179.04 v1(51.43,177.86) ; 51.29,179.18 45.46,179.18 36.58,188.06 36.58,203.2 40.55,207.16 165.01,207.16 170.45,201.71 170.45,181.88 165.06,176.49 v1(165.06,175.34) 173.23,175.34 174.89,177 192.52,177 193.52,176.01 204.31,176.01 205.64,177.34 230.4,177.34 v1(232.8,174.95) ; 51.29,179.18 73.68,179.18 77.73,175.13 v1(80.27,175.13) ; 209.71,15.87 209.71,17.66 208.17,19.2 194.41,19.2 v1(193.61,20) 185.11,20 182.09,16.99 114.69,16.99 v1(113.39,18.29) 113.07,18.61 67.33,18.61 52.3,33.64 52.3,96.51 66.28,110.5 66.28,119.79 v1(51.53,134.55) ; v1(181.39,56.82) 181.39,55.22 189.35,47.26 189.35,29.26 v1(193.61,25) ; v1(235.88,56.26) 236.26,55.88 236.26,14.44 v1(236.17,14.35) ; v1(110.22,57.61) 110.22,31.48 113.39,28.31 v1(113.39,21.99)
  ART03 w0.762: v1(51.43,177.86) 51.43,134.65 v1(51.53,134.55) ; v1(113.39,18.29) v1(113.39,21.99)
  ART03 w0.78: v1(193.61,25) v1(193.61,20)
  BOTTOM w0.508: R19.1 v1(232.8,174.95) ; R54.1 236.11,56.49 v1(235.88,56.26) ; v1(110.22,57.61) 111.4,57.61 R65.1 ; R3.1 v1(80.27,175.13) ; R26.1 v1(165.06,175.34)
  BOTTOM w0.762: C75.1 209.9,14.35 v1(236.17,14.35) 239.52,11 263.62,11 J6.8 ; R41.1 181.71,57.13 v1(181.39,56.82)
  vias: v1(286.66,6.83)
VL: length 86
  TOP w0.254: v1(270.36,11.1) 273.69,14.43 315.06,14.43 317.99,11.51 317.99,11.51 318.4,11.1 v1(319.21,11.1)
  GND02 w0.254: J6.7 269.49,5.38 269.49,10.23 v1(270.36,11.1)
  BOTTOM w0.254: v1(319.21,11.1) 320.4,12.29 330.62,12.29 334.55,8.36 339.15,8.36 341.99,5.52 R138.2
VN: length 85.9
  TOP w0.254: v1(318.27,12.19) 315.4,15.06 273.08,15.06 269.49,11.48 269.49,5.13 J6.9
  BOTTOM w0.254: R144.2 339.54,8.94 334.69,8.94 330.83,12.8 320.07,12.8 319.46,12.19 v1(318.27,12.19)
XRS: length 5.6
  TOP w0.508: R148.1 294.02,9.12 293.09,9.12 292.15,10.06 289.25,10.06 R150.1

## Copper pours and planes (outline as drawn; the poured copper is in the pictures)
AGND on TOP (solid shape): 193.39,14.76 193.39,13.11 194.28,12.22 199.36,12.22 200.63,13.49 204.82,13.49 206.47,11.84 210.92,11.84 211.55,11.2 211.55,9.55 210.66,8.66 205.84,8.66 205.46,9.04 205.46,9.42 205.2,9.68 200.76,9.68 200.74,9.69 200.21,9.69 199.38,10.52 194.23,10.52 193.39,9.68 193.39,7.9 193.26,7.77 186.66,7.77 186.28,8.15 186.28,14.76 186.41,14.88 193.26,14.88
AGND on BOTTOM (solid shape): 184.55,60.84 184.55,59.78 184.54,59.76 181.74,59.76 181.37,60.13 181.37,60.31 181.36,60.31 181.23,60.45 178.73,60.45 178.37,60.09 178.37,58.31 178.36,58.3 177.36,58.3 177.11,58.06 177.11,56.5 177.05,56.44 176.19,56.44 176.11,56.52 176.11,59.64 175.99,59.76 174.1,59.76 173.96,59.9 173.96,60.99 174.11,61.13 184.26,61.13
AGND on BOTTOM (solid shape): 239.27,60.67 239.27,59.23 239.16,59.12 236.74,59.12 236.58,59.28 236.58,60.17 236.27,60.48 233.79,60.48 233.51,60.2 233.51,58.38 233.47,58.33 232.52,58.33 232.17,57.98 232.17,56.53 232.13,56.49 231.3,56.49 231.21,56.58 231.21,59.29 231.03,59.46 229.25,59.46 229.12,59.6 229.12,60.93 229.34,61.16 238.78,61.16
AGND on BOTTOM (solid shape): 113.89,62.1 113.89,60.52 113.82,60.45 111.51,60.45 110.75,61.21 107.83,61.21 107.7,61.09 107.7,59.18 107.43,58.91 106.7,58.91 106.05,58.26 106.05,57.39 105.95,57.29 105.1,57.29 105.07,57.33 105.07,58.35 105.64,58.92 105.64,60.28 105.47,60.45 102.97,60.45 102.84,60.58 102.84,61.9 103.17,62.23 113.76,62.23
AGND on BOTTOM (solid shape): 308.76,12.04 308.76,10.64 308.63,10.52 304.31,10.52 304.06,10.77 295.55,10.77 295.24,10.46 293.06,10.46 292.4,9.8 292.4,4.57 293.26,3.71 296.69,3.71 296.77,3.63 297.84,3.63 298.22,3.25 305.38,3.25 305.76,2.87 305.76,1.55 305.35,1.14 288.59,1.14 287.68,2.06 287.68,3.61 287.78,3.71 289.43,3.71 289.44,3.72 289.64,3.72 289.86,3.94 289.86,6.58 289.96,6.68 290.57,6.68 290.65,6.76 290.65,8.79 290.55,8.89 289.89,8.89 289.78,8.99 289.78,10.31 289.63,10.46 287.73,10.46 286.41,11.79 283.87,11.79 283.87,11.78 283.76,11.78 283.2,11.23 283.2,1.83 283.1,1.73 281.58,1.73 281.45,1.85 281.45,12.29 282.34,13.18 307.61,13.18
AGND on BOTTOM: 77.35,170.94 77.22,171.07 77.22,172.47 77.35,172.59 79.51,172.59 80.53,171.58 82.94,171.58 83.19,171.83 83.19,173.61 83.32,173.74 83.76,173.74 84.16,174.13 84.16,175.65 84.25,175.74 85.13,175.74 85.22,175.66 85.22,172.72 85.35,172.59 87.25,172.59 87.48,172.36 87.48,171.27 87.15,170.94
AGND on BOTTOM: 240.3,172.56 240.09,172.77 238.47,172.77 238.13,173.11 238.13,175.56 238,175.7 237.09,175.7 237.03,175.64 237.03,174.06 236.97,173.99 235.85,173.99 235.72,173.86 235.72,171.96 235.47,171.7 233.03,171.7 232.26,172.47 229.75,172.47 229.62,172.34 229.62,171.2 229.88,170.94 240.18,170.94 240.3,171.06
AGND on BOTTOM: 170.47,172.89 170.35,173.01 170.35,175.8 170.24,175.91 169.37,175.91 169.3,175.85 169.3,174.19 169.23,174.12 168.03,174.12 167.9,173.99 167.9,171.98 167.71,171.79 165.27,171.79 165.11,171.96 165.11,172.45 164.84,172.72 161.93,172.72 161.81,172.59 161.81,171.7 162.19,171.32 172.6,171.32 172.86,171.58 172.86,172.75 172.72,172.89
AGND on GND02: outline of 153 points within 33.79,0.43 407.86,209.8
AGND on ART05: 110.73,1.32 104.12,7.92 101.28,7.92 96.76,12.45 96.76,15.67 98.03,16.94 101.12,16.94 101.48,16.59 134.03,16.59 134.65,17.21 134.65,21.54 134.97,21.86 138.31,21.86 138.63,21.54 138.63,17.7 139.75,16.59 150.96,16.59 150.97,16.58 152.88,18.49 209.16,18.49 211.22,16.43 212.07,15.59 240.4,15.59 242.67,13.31 342.12,13.31 342.83,12.6 342.83,3.81 342.15,3.12 337.4,3.12 331.12,9.4 327.36,9.4 327.11,9.14 327.11,1.62 326.81,1.32
P6.5V on TOP (solid shape): 199.61,8.41 204.95,8.41 205.2,8.15 206.93,8.15 207.28,7.81 207.28,6.9 207.13,6.76 195.8,6.76 194.66,7.9 194.66,9.8 194.79,9.93 198.09,9.93
A_1.2V on BOTTOM (solid shape): 296.53,9.9 308.88,9.9 309.13,9.65 309.13,7.98 308.87,7.72 296.37,7.72 296.21,7.88 295.56,8.53 293.77,8.53 293.54,8.75 293.54,8.95 293.57,9.12 293.54,9.29 293.54,10.04 293.7,10.2 296.23,10.2
A_1.2V on TOP: 282.19,11.05 280.06,8.92 280.06,5 279.67,4.62 278.4,4.62 278.09,4.94 278.09,10.12 281.25,13.28 295.8,13.28 299.21,9.88 308.87,9.88 309.13,9.63 309.13,7.77 308.87,7.52 297.81,7.52 294.28,11.05
A_1.2V on BOTTOM: 272.69,4.88 277.26,4.88 278.4,6.02 279.8,6.02 280.06,5.77 280.06,3.35 279.29,2.59 272.69,2.59 272.31,2.97 272.31,4.5
A_3.3V on BOTTOM (solid shape): 303.54,7.23 304.93,7.23 305.33,6.83 305.33,4.93 305.03,4.63 298.16,4.63 298.14,4.63 298.12,4.62 297.76,4.26 297.74,4.25 297.72,4.24 296.41,4.24 296.39,4.24 296.38,4.23 296.14,3.99 296.12,3.98 296.1,3.97 293.59,3.97 293.57,3.98 293.56,3.99 293.46,4.09 293.45,4.11 293.44,4.13 293.44,5.51 293.45,5.53 293.46,5.55 293.55,5.64 293.56,5.65 293.58,5.65 295.4,5.65 295.42,5.66 295.44,5.67 295.79,6.02 295.8,6.04 295.8,6.06 295.8,6.56 295.81,6.58 295.82,6.59 296.44,7.22 296.46,7.23 296.48,7.23 303.53,7.23
A_3.3V on TOP: 305.28,5.87 300.2,0.79 278.05,0.79 273.27,5.56 272.87,5.56 272.31,6.12 272.31,6.96 272.71,7.37 274.98,7.37 279.17,3.17 298.9,3.17 302.84,7.11 305.05,7.11 305.28,6.88
AC_L_SAMPLE on ART05 (solid shape): 465.4,164.39 465.4,6.83 459.75,1.18 421.98,1.18 407.67,15.49 407.67,30.14 409.69,32.17 432.06,32.17 442.79,42.9 442.79,165.33 444.39,166.93 462.86,166.93
AC_L_SAMPLE on TOP: 432.02,32.09 409.8,32.09 407.85,30.14 407.85,15.46 414.61,8.71 455.93,8.71 465.4,18.17 465.4,164.39 462.86,166.93 444.39,166.93 442.79,165.33 442.79,42.87
AC_L_SAMPLE on BOTTOM: 410.6,32.14 432,32.14 442.74,42.89 442.74,165.35 444.37,166.98 462.88,166.98 465.45,164.41 465.45,6.81 459.77,1.13 422.11,1.13 409.07,14.16 409.07,30.62
AC_L_SAMPLE on GND02, ART03, ART04: 407.75,15.42 407.75,30.18 409.75,32.19 431.97,32.19 442.69,42.91 442.69,165.37 444.35,167.03 462.9,167.03 465.5,164.43 465.5,6.79 459.79,1.08 422.09,1.08
AC_SW on TOP (solid shape): 225.94,150.3 225.94,143.32 228.28,140.99 244.13,140.99 244.61,141.47 244.61,145.09 245.12,145.6 245.12,150.3 245.63,150.81 246.65,150.81 247.15,150.3 247.15,143.33 248.58,141.9 250.58,139.9 255.9,139.9 264.15,133.56 271.18,141.22 271.17,141.56 271.15,141.9 298.29,141.9 299.94,140.25 299.94,109.93 296.27,106.26 269.47,106.26 261.75,98.55 261.1,98.63 260.45,98.66 256.71,97.69 253.91,95.02 240.78,95.02 240.4,94.64 240.4,93.5 243,90.89 243,82.2 242.45,81.65 238.36,81.65 238.1,81.91 238.1,87.87 235.29,90.68 221.96,90.68 221.36,90.08 221.36,82.5 220.55,81.69 216.95,81.69 216.79,81.85 216.79,87.36 217.46,89.11 217.68,90.96 217.53,92.49 217.08,93.95 232.6,109.47 232.6,114.3 232.76,114.46 232.76,125.01 222.9,134.87 222.9,142.49 222.91,142.5 222.91,144.62 223.91,145.62 223.91,150.3 224.42,150.81 225.44,150.81
AC_SW on GND02 (solid shape): 225.94,150.3 225.94,143.32 228.28,140.99 244.13,140.99 244.61,141.47 244.61,145.09 245.12,145.6 245.12,150.3 245.63,150.81 246.65,150.81 247.15,150.3 247.15,143.33 248.58,141.9 258.14,141.9 258.11,141.56 258.1,141.22 263.48,135.84 268.87,141.22 268.86,141.56 268.83,141.9 298.29,141.9 299.94,140.25 299.94,109.93 296.27,106.26 269.47,106.26 259.46,96.26 258.1,95.81 256.91,95.02 240.78,95.02 240.4,94.64 240.4,93.5 243,90.89 243,82.2 242.45,81.65 238.36,81.65 238.1,81.91 238.1,87.87 235.65,90.32 221.6,90.32 221.36,90.08 221.36,82.5 220.55,81.69 216.95,81.69 216.79,81.85 216.79,93.66 232.6,109.47 232.6,114.3 232.76,114.46 232.76,125.01 222.9,134.87 222.9,142.49 222.91,142.5 222.91,144.62 223.91,145.62 223.91,150.3 224.42,150.81 225.44,150.81
AC_SW on ART03 (solid shape): 225.94,150.3 225.94,143.32 228.28,140.99 244.13,140.99 244.61,141.47 244.61,145.09 245.12,145.6 245.12,150.3 245.63,150.81 246.65,150.81 247.15,150.3 247.15,143.33 248.58,141.9 258.14,141.9 258.11,141.56 258.1,141.22 263.48,135.84 268.87,141.22 268.86,141.56 268.83,141.9 298.29,141.9 299.94,140.25 299.94,109.93 296.27,106.26 269.47,106.26 259.46,96.26 258.1,95.81 256.91,95.02 240.78,95.02 240.4,94.64 240.4,93.5 243,90.89 243,82.2 242.45,81.65 238.36,81.65 238.1,81.91 238.1,87.87 235.65,90.32 221.6,90.32 221.36,90.08 221.36,82.5 220.55,81.69 216.95,81.69 216.79,81.85 216.79,93.66 232.6,109.47 232.6,114.3 232.76,114.46 232.76,125.01 222.9,134.87 222.9,142.49 222.91,142.5 222.91,144.62 223.91,145.62 223.91,150.3 224.42,150.81 225.44,150.81
DC+ on BOTTOM (solid shape): 69.41,190.87 79.61,190.87 81.09,189.38 77.46,185.75 66.31,185.75 61.95,190.11 64.33,192.48 67.79,192.48
DC+ on ART04 (solid shape): 60.11,196.81 126.06,196.81 133.26,189.6 133.26,164.05 132.46,163.25 122.62,163.25 121.2,164.67 91.28,164.67 89.29,166.66 89.29,178.93 88.17,180.05 46.85,180.05 41.7,185.19 38.38,188.51 38.38,201.84 40.23,203.69 53.22,203.69
DC+ on BOTTOM: 133.26,163.92 133.26,189.48 132.39,190.34 103.9,190.34 101.37,192.87 101.37,192.87 99.94,194.29 77.32,194.29 77.19,194.42 62.37,194.42 53.22,203.56 44.09,203.56 44.05,203.52 40.2,203.52 38.39,201.71 38.39,188.35 41.7,185.03 45.09,181.64 92.6,181.64 94.06,180.19 94.06,169.28 97.25,166.09 119.65,166.09 121.2,164.54 122.62,163.12 132.46,163.12
DC+ on GND02: 85.83,153.41 85.83,145.73 86.54,145.02 90.5,145.02 90.85,145.38 90.85,150.62 93.1,152.86 105.83,152.86 107.44,151.25 107.44,145.76 108.07,145.14 111.72,145.14 112.1,145.52 112.1,151.91 113.01,152.82 127.57,152.82 128.43,151.96 128.43,145.68 128.9,145.21 132.89,145.21 133.26,145.58 133.26,189.76 126.34,196.68 60.11,196.68 53.22,203.56 40.21,203.56 38.4,201.74 38.4,188.37 41.7,185.07 46.85,179.92 87.66,179.92 87.66,180.92 87.59,181 87.59,181.81 90.23,181.81 91.78,180.26 91.78,172.97 89.29,170.48 89.29,156.86
DC+ on ART03: 85.83,153.41 85.83,145.73 86.54,145.02 90.5,145.02 90.85,145.38 90.85,150.62 93.1,152.86 105.83,152.86 107.44,151.25 107.44,145.76 108.07,145.14 111.72,145.14 112.1,145.52 112.1,151.91 113.01,152.82 127.57,152.82 128.43,151.96 128.43,145.68 128.9,145.21 132.89,145.21 133.26,145.58 133.26,189.48 126.06,196.68 60.15,196.68 53.27,203.56 44.09,203.56 44.06,203.53 40.19,203.53 38.39,201.73 38.39,188.48 41.7,185.17 46.95,179.92 88.17,179.92 89.29,178.8 89.29,156.86
DC+ on ART05: 133.26,163.92 133.26,189.48 129.7,193.03 106.94,193.03 103.29,196.68 60.11,196.68 53.22,203.56 40.23,203.56 38.38,201.71 38.38,188.39 41.7,185.07 46.85,179.92 88.17,179.92 89.29,178.8 89.29,166.53 91.28,164.54 121.2,164.54 122.62,163.12 132.46,163.12
DC- on TOP (solid shape): 124.37,66.04 124.37,62.15 124.23,62.01 124.23,41.85 122.32,39.94 117.7,39.94 116.28,41.36 116.28,52.22 116.44,52.38 116.44,52.44 116.75,52.75 116.75,56.79 116.74,56.79 116.74,62.86 121.32,67.44 122.97,67.44
DC- on GND02 (solid shape): 100.05,54.17 100.05,53.53 100.1,53.47 100.1,48.92 102.28,46.73 102.28,40.6 101.62,39.94 77.07,39.94 77.06,39.93 66.72,39.93 64.49,42.17 64.49,54.91 66.36,56.79 97.43,56.79
DC- on ART03 (solid shape): outline of 974 points within 78.39,40.29 126.49,86.93
DC- on ART04 (solid shape): 83.9,86.79 83.9,77.9 83.65,77.65 82,77.65 81.74,77.9 81.74,86.79 82,87.04 83.65,87.04
DC- on ART04 (solid shape): 105.19,86.73 105.19,77.84 104.94,77.59 103.28,77.59 103.03,77.84 103.03,86.73 103.28,86.99 104.94,86.99
DC- on ART04 (solid shape): 126.47,86.6 126.47,77.71 126.22,77.45 124.57,77.45 124.31,77.71 124.31,86.6 124.57,86.85 126.22,86.85
DC- on ART04 (solid shape): outline of 976 points within 78.39,40.29 126.49,86.93
DC- on ART03: 119.78,39.94 77.07,39.94 77.06,39.93 68.07,39.93 67.97,39.84 64.11,39.84 58.71,34.43 58.71,18.18 57.22,16.69 42.86,16.69 42.8,16.76 34.69,16.76 33.41,18.03 33.41,34.1 56.13,56.82 94.14,56.82 95.97,58.65 111.38,58.65 120.16,67.44 122.97,67.44 124.37,66.04 124.37,62.15 121.12,58.9 121.12,41.27 120.7,40.85
DC- on ART04: 119.78,39.94 77.07,39.94 77.06,39.93 68.07,39.93 67.97,39.84 64.11,39.84 58.71,34.43 58.71,18.18 57.22,16.69 34.75,16.69 33.41,18.03 33.41,34.1 56.24,56.94 114.75,56.94 122.69,64.87 122.69,67.44 122.97,67.44 124.37,66.04 124.37,62.15 121.12,58.9 121.12,41.27 120.7,40.85
DC- on ART05: 119.78,39.94 77.07,39.94 77.06,39.93 68.07,39.93 67.97,39.84 64.11,39.84 58.71,34.43 58.71,18.18 57.22,16.69 34.75,16.69 33.41,18.03 33.41,34.1 56.26,56.95 94.27,56.95 96.81,59.49 96.81,61.62 114.85,61.62 120.66,67.44 122.97,67.44 124.37,66.04 124.37,62.15 121.12,58.9 121.12,41.27 120.7,40.85
DC_N on TOP (solid shape): 169.62,70.42 169.62,52 171.62,50 177.61,50 179.61,48 179.61,44 177.61,42 168.88,42 167.41,40.54 153.46,40.54 147.61,46.39 147.61,66.58 147.62,66.59 147.62,70.67 149.58,72.63 167.41,72.63
DC_N on GND02 (solid shape): outline of 138 points within 143.59,40.54 190.95,86.95
DC_N on ART03 (solid shape): outline of 245 points within 143.59,53.94 190.95,86.95
DC_N on ART03 (solid shape): outline of 1074 points within 145.52,145.37 196.44,177.73
DC_N on ART04 (solid shape): outline of 1074 points within 145.52,145.37 196.44,177.73
DC_N on TOP: 416.46,36.88 410.45,42.89 410.45,170.71 408.53,172.63 404.43,176.73 270.7,176.73 260.41,187.03 183.47,187.03 182.58,187.91 182.58,197.65 219.15,197.65 221.03,199.53 233.22,199.53 235.38,201.69 262.33,201.69 264.49,199.53 457.39,199.53 460.85,196.07 460.85,179.69 458.96,177.8 458.96,177.8 457.58,176.42 442.17,176.42 437.59,171.85 437.59,46.73 427.75,36.88
DC_N on BOTTOM: 218.37,195.71 175.63,195.71 170.37,190.44 155.35,190.44 145.47,180.56 145.47,165.61 147.38,163.7 152.97,163.7 156.29,167.03 156.29,174.51 165.06,183.28 175.06,183.28 181.22,189.43 218.73,189.43 219.97,190.68 219.97,194.11
DC_N on GND02: 416.46,36.88 408.53,44.82 408.53,172.63 404.43,176.73 270.71,176.73 267.28,180.16 267.19,180.16 262.09,185.26 182.72,185.26 180.88,187.1 180.88,196.59 181.8,197.51 219.43,197.51 221.45,199.53 457.39,199.53 460.85,196.07 460.85,182.73 455.92,177.8 454.54,176.42 440.78,176.42 437.59,173.24 437.59,46.73 427.75,36.88
DC_N on ART03: 410.77,197.57 458,197.57 461.28,194.28 461.28,183.18 454.77,176.67 454.74,176.67 454.64,176.57 440.95,176.57 437.66,173.28 437.66,46.74 427.68,36.75 427.48,36.75 427.28,36.56 418,36.56 417.96,36.52 417.76,36.72 417.76,36.75 390.33,36.75 385.56,31.98 367.28,13.7 245.72,13.7 235.85,23.56 234.8,23.56 219.77,38.59 148.53,38.59 146.04,41.07 146.04,60.5 147.96,62.41 171.24,62.41 174.21,65.38 174.47,65.38 174.42,65.33 174.42,63.71 174.87,63.25 188.35,63.25 195.6,56.01 270.64,56.01 277.5,49.15 362.21,49.15 389.69,76.63 405.51,76.63 408.55,79.68 408.55,172.61 404.43,176.73 299.84,176.73 291.31,168.2 211.25,168.2 211.14,168.09 189.77,168.09 187.52,170.34 175.22,170.34 173.2,168.32 159.18,168.32 155.06,164.2 147.48,164.2 145.52,166.16 145.52,181.71 155.94,192.13 155.94,192.16 161.33,197.55 410.75,197.55
